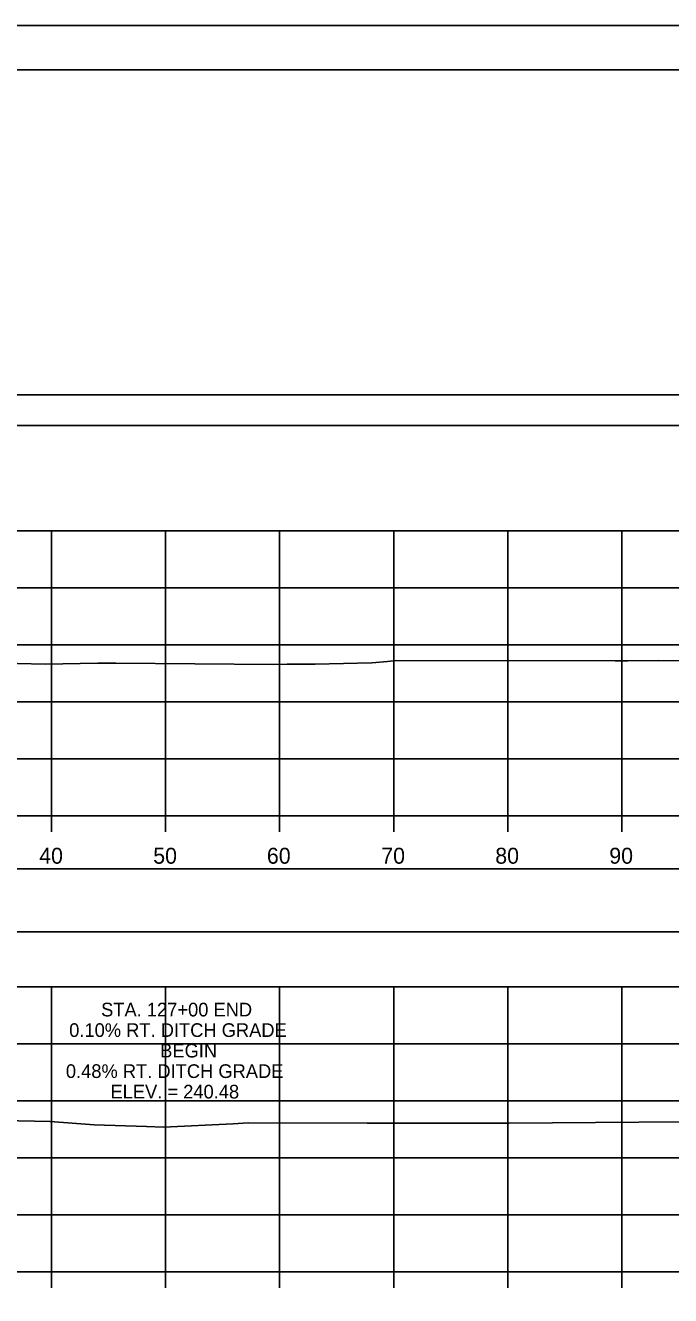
# Model space of a CAD drawing. Extents: x 1369627 to 1374022, y 380035 to 398173.
# Drawn here: x 1370216.9 to 1370273.5, y 382270.1 to 382381.6 of the extents above; entities that cross this region are included whole.
import ezdxf

# ---------------------------------------------------------------- set-up
doc = ezdxf.new("R2010")
doc.units = 0
for name, color, linetype in [('Default', 7, 'Continuous'), ('R_Axis', 7, 'Continuous'), ('R_Axis Annot', 7, 'Continuous'), ('R_Border', 7, 'Continuous'), ('R_Exist Surface', 7, 'Continuous'), ('R_Grid', 7, 'Continuous'), ('R_No Plot', 7, 'Continuous'), ('R_Xsect Elev', 7, 'Continuous')]:
    doc.layers.add(name, color=color, linetype=linetype)

msp = doc.modelspace()

# ---------------------------------------------------------------- linework, layer by layer
at = {"layer": 'Default'}
for points in [[(1370029.24, 382346.49), (1370329.24, 382346.49), (1370329.24, 382349.19), (1370029.24, 382349.19)], [(1370029.24, 382302.06), (1370329.24, 382302.06), (1370329.24, 382307.59), (1370029.24, 382307.59)]]:
    msp.add_lwpolyline(points, close=True, dxfattribs=at)
at = {"layer": 'R_Axis'}
for p, q in [((1370029.24, 382312.24), (1370329.24, 382312.24)), ((1370219.24, 382310.84), (1370219.24, 382312.24)), ((1370229.24, 382310.84), (1370229.24, 382312.24)), ((1370239.24, 382310.84), (1370239.24, 382312.24)), ((1370249.24, 382310.84), (1370249.24, 382312.24)), ((1370259.24, 382310.84), (1370259.24, 382312.24)), ((1370269.24, 382310.84), (1370269.24, 382312.24)), ((1370029.24, 382272.24), (1370329.24, 382272.24)), ((1370219.24, 382270.84), (1370219.24, 382272.24)), ((1370229.24, 382270.84), (1370229.24, 382272.24)), ((1370239.24, 382270.84), (1370239.24, 382272.24)), ((1370249.24, 382270.84), (1370249.24, 382272.24)), ((1370259.24, 382270.84), (1370259.24, 382272.24)), ((1370269.24, 382270.84), (1370269.24, 382272.24))]:
    msp.add_line(p, q, dxfattribs=at)
at = {"layer": 'R_Border'}
msp.add_line((1370021.24, 382377.7), (1370337.42, 382377.7), dxfattribs=at)
at = {"layer": 'R_Exist Surface'}
for points in [[(1370211.36, 382325.71), (1370218.66, 382325.56), (1370223.3, 382325.64), (1370224.88, 382325.64), (1370238.73, 382325.53), (1370239.89, 382325.54), (1370242.36, 382325.54), (1370247.32, 382325.65), (1370248.69, 382325.77), (1370249.46, 382325.86), (1370268.67, 382325.85), (1370269.79, 382325.85), (1370272.48, 382325.86), (1370292.48, 382325.84), (1370292.52, 382325.85), (1370313.91, 382325.64), (1370314.37, 382325.64), (1370317.57, 382325.36), (1370317.83, 382325.35), (1370328.11, 382325.44), (1370329.24, 382325.45)], [(1370214.97, 382285.51), (1370219.1, 382285.42), (1370222.98, 382285.12), (1370227.57, 382284.97), (1370229.04, 382284.92), (1370235.16, 382285.21), (1370236.48, 382285.3), (1370246.91, 382285.28), (1370259.37, 382285.28), (1370278.3, 382285.41), (1370290.07, 382285.4), (1370297.07, 382285.15), (1370297.4, 382285.15), (1370302.16, 382285.45), (1370302.24, 382285.5), (1370305.38, 382285.56), (1370308.8, 382285.42), (1370309.78, 382285.36), (1370313.3, 382285.39), (1370321.58, 382285.45), (1370327.35, 382285.49), (1370329.24, 382285.5)]]:
    msp.add_lwpolyline(points, dxfattribs=at)
at = {"layer": 'R_Grid'}
for p, q in [((1370029.24, 382337.24), (1370329.24, 382337.24)), ((1370219.24, 382312.24), (1370219.24, 382337.24)), ((1370229.24, 382312.24), (1370229.24, 382337.24)), ((1370239.24, 382312.24), (1370239.24, 382337.24)), ((1370249.24, 382312.24), (1370249.24, 382337.24)), ((1370259.24, 382312.24), (1370259.24, 382337.24)), ((1370269.24, 382312.24), (1370269.24, 382337.24)), ((1370029.24, 382332.24), (1370329.24, 382332.24)), ((1370029.24, 382327.24), (1370329.24, 382327.24)), ((1370029.24, 382322.24), (1370329.24, 382322.24)), ((1370029.24, 382317.24), (1370329.24, 382317.24)), ((1370029.24, 382312.24), (1370329.24, 382312.24)), ((1370029.24, 382297.24), (1370329.24, 382297.24)), ((1370219.24, 382272.24), (1370219.24, 382297.24)), ((1370229.24, 382272.24), (1370229.24, 382297.24)), ((1370239.24, 382272.24), (1370239.24, 382297.24)), ((1370249.24, 382272.24), (1370249.24, 382297.24)), ((1370259.24, 382272.24), (1370259.24, 382297.24)), ((1370269.24, 382272.24), (1370269.24, 382297.24)), ((1370029.24, 382292.24), (1370329.24, 382292.24)), ((1370029.24, 382287.24), (1370329.24, 382287.24)), ((1370029.24, 382282.24), (1370329.24, 382282.24)), ((1370029.24, 382277.24), (1370329.24, 382277.24)), ((1370029.24, 382272.24), (1370329.24, 382272.24))]:
    msp.add_line(p, q, dxfattribs=at)
at = {"layer": 'R_No Plot'}
msp.add_line((1370008.84, 382381.59), (1370342.17, 382381.59), dxfattribs=at)
for points in [[(1370008.83, 382381.59), (1370342.17, 382381.59), (1370342.17, 382168.25), (1370008.83, 382168.25)], [(1370255.16, 382377.7), (1370274.78, 382377.7), (1370274.78, 382367.82), (1370290.89, 382367.82), (1370314.09, 382367.82), (1370314.09, 382335.15), (1370337.3, 382335.15), (1370337.42, 382172.24), (1370021.24, 382172.24), (1370021.24, 382377.7)]]:
    msp.add_lwpolyline(points, close=True, dxfattribs=at)

# ---------------------------------------------------------------- texts
at = {"layer": 'R_Axis Annot'}
for s, p in [('40', (1370218.15, 382308.04)), ('50', (1370228.15, 382308.04)), ('60', (1370238.12, 382308.04)), ('70', (1370248.15, 382308.04)), ('80', (1370258.15, 382308.04)), ('90', (1370268.15, 382308.04))]:
    msp.add_text(s, height=1.4, dxfattribs=at).set_placement(p)
at = {"layer": 'R_Xsect Elev'}
for s, p in [('STA. 127+00 END', (1370223.58, 382294.64)), ('0.10% RT. DITCH GRADE', (1370220.78, 382292.84)), ('BEGIN', (1370228.76, 382291.04)), ('0.48% RT. DITCH GRADE', (1370220.49, 382289.24)), ('ELEV. = 240.48', (1370224.4, 382287.44))]:
    msp.add_text(s, height=1.2, dxfattribs=at).set_placement(p)

doc.saveas('drawing.dxf')
